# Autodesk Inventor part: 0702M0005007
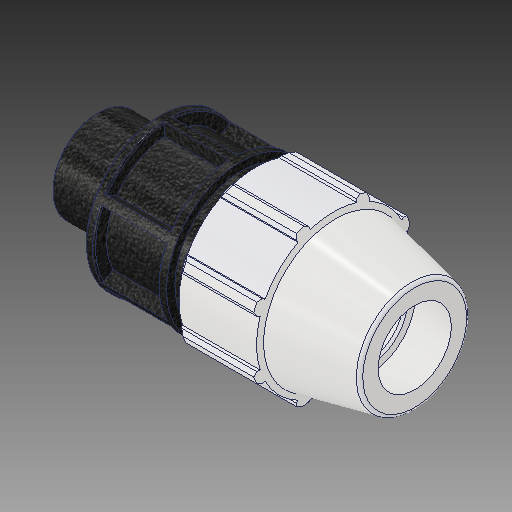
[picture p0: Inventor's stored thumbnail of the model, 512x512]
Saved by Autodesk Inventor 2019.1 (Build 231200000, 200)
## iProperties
Created: 2017-02
Part Number: 0702M0005007
Material: PVC-Piping
Description: PLASSON MALE ADAPTOR 1/2'' - 3/4''M
Document SubType Name: Modeling
Designer: KIM
Mass: 92.6774 g
Surface Area: 199.44 cm^2
Volume: 66.1981 cm^3
Density: 1.4 g/cm^3
Appearance: PTFE
Author: KIM
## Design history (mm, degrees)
derived "0702M0.ipt"
feature "Solid1::0702M0.ipt"
tag "TaggingFeature1"
body "Solid1"
other parameters: "d2" = 21.2, "d4" = 13.13543, "d5" = 22.987, "d7" = 48.006, "d8" = 36.0045, "d9" = 13.13543, "d11" = 2.62709, "d12" = 38.4048, "d13" = 120 deg, "d14" = 31.8, "d15" = 12 deg, "d16" = 43.2054, "d18" = 1.06, "d19" = 35 deg, "d20" = 17.5 deg, "d21" = 44.64558, "d23" = 0, "d25" = 360 deg, "d27" = 0.96012, "d34" = 2.4003, "d36" = 0, "d42" = 22.987, "d43" = 1.44018, "d46" = 0.636, "d49" = 70.104, "d51" = 91.948, "d52" = 18.034, "d53" = 0.424, "d55" = 360 deg, "d57" = 26.441, "d58" = 18.5087, "d59" = 18.3896, "d_" = 21.2, "E_" = 48.006, "H_" = 91.948, "l_" = 70.104, "l_2" = 18.034, "G_" = 26.441
